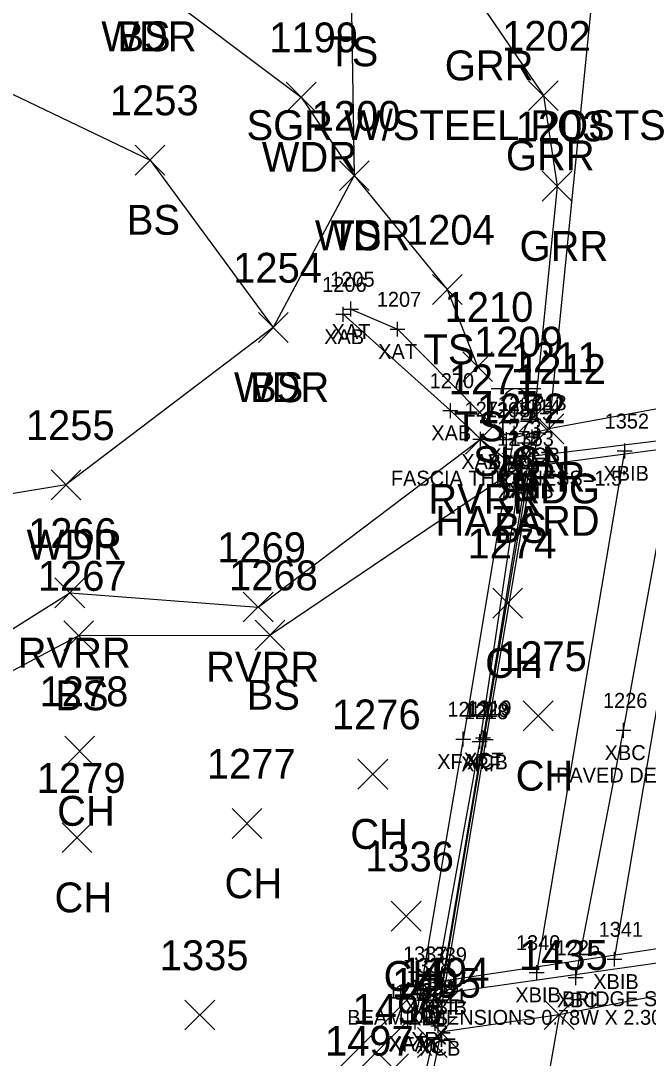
# Model space of a CAD drawing. Extents: x 1678553 to 1680768, y 787260 to 792325.
# Drawn here: x 1678655.8 to 1678697.8, y 787518.8 to 787588.2 of the extents above; entities that cross this region are included whole.
import ezdxf

# ---------------------------------------------------------------- set-up
doc = ezdxf.new("R2010")
doc.units = 0
for name, color, linetype in [('B_A', 7, 'Continuous'), ('B_C', 7, 'Continuous'), ('B_I', 7, 'Continuous'), ('B_TIC', 7, 'Continuous'), ('BB', 7, 'Continuous'), ('BDC', 7, 'Continuous'), ('BELB', 7, 'Continuous'), ('BF', 7, 'Continuous'), ('BR', 7, 'Continuous'), ('BSE', 7, 'Continuous'), ('BSUBM', 7, 'Continuous'), ('Default', 7, 'Continuous'), ('L_A', 7, 'Continuous'), ('L_I', 7, 'Continuous'), ('L_TIC', 7, 'Continuous'), ('LAWA', 7, 'Continuous'), ('LAWE', 7, 'Continuous'), ('LELB', 7, 'Continuous'), ('P_A', 7, 'Continuous'), ('P_I', 7, 'Continuous'), ('P_TIC', 7, 'Continuous'), ('PEU', 7, 'Continuous'), ('PRC', 7, 'Continuous'), ('R_A', 7, 'Continuous'), ('R_C', 7, 'Continuous'), ('R_I', 7, 'Continuous'), ('R_TIC', 7, 'Continuous'), ('RGR', 7, 'Continuous'), ('S_A', 7, 'Continuous'), ('S_C', 7, 'Continuous'), ('S_I', 7, 'Continuous'), ('SSGN', 7, 'Continuous')]:
    doc.layers.add(name, color=color, linetype=linetype)

msp = doc.modelspace()

# ---------------------------------------------------------------- linework, layer by layer
at = {"layer": 'B_TIC'}
for p, q in [((1678677.4, 787568.583), (1678677.475, 787568.583)), ((1678677.914, 787568.928), (1678677.989, 787568.928)), ((1678681.033, 787567.585), (1678681.109, 787567.585)), ((1678684.578, 787562.134), (1678684.653, 787562.134)), ((1678686.588, 787560.22), (1678686.664, 787560.22)), ((1678688.339, 787560.19), (1678688.414, 787560.19)), ((1678688.85, 787560.608), (1678688.925, 787560.608)), ((1678689.542, 787559.98), (1678689.617, 787559.98)), ((1678690.053, 787560.377), (1678690.129, 787560.377)), ((1678690.446, 787560.654), (1678690.521, 787560.654)), ((1678696.259, 787559.432), (1678696.334, 787559.432)), ((1678689.047, 787558.968), (1678689.122, 787558.968)), ((1678689.052, 787558.274), (1678689.127, 787558.274)), ((1678689.879, 787558.254), (1678689.955, 787558.254)), ((1678696.175, 787540.725), (1678696.25, 787540.725)), ((1678685.437, 787540.133), (1678685.512, 787540.133)), ((1678686.54, 787539.97), (1678686.615, 787539.97)), ((1678686.764, 787540.216), (1678686.84, 787540.216)), ((1678686.941, 787540.102), (1678687.017, 787540.102)), ((1678695.575, 787525.394), (1678695.65, 787525.394)), ((1678690.359, 787524.501), (1678690.434, 787524.501)), ((1678692.973, 787524.163), (1678693.048, 787524.163)), ((1678682.753, 787523.742), (1678682.828, 787523.742)), ((1678684.062, 787523.687), (1678684.137, 787523.687)), ((1678683.003, 787522.966), (1678683.078, 787522.966)), ((1678681.721, 787521.255), (1678681.796, 787521.255)), ((1678682.207, 787521.192), (1678682.283, 787521.192)), ((1678683.19, 787521.52), (1678683.266, 787521.52)), ((1678683.552, 787521.092), (1678683.628, 787521.092)), ((1678683.768, 787520.937), (1678683.843, 787520.937))]:
    msp.add_line(p, q, dxfattribs=at)
for points in [[(1678677.396, 787568.083), (1678677.396, 787569.083)], [(1678677.91, 787568.428), (1678677.91, 787569.428)], [(1678676.896, 787568.583), (1678677.896, 787568.583)], [(1678677.41, 787568.928), (1678678.41, 787568.928)], [(1678681.03, 787567.085), (1678681.03, 787568.085)], [(1678680.53, 787567.585), (1678681.53, 787567.585)], [(1678684.074, 787562.134), (1678685.074, 787562.134)], [(1678684.574, 787561.634), (1678684.574, 787562.634)], [(1678686.585, 787559.72), (1678686.585, 787560.72)], [(1678688.335, 787559.69), (1678688.335, 787560.69)], [(1678688.846, 787560.108), (1678688.846, 787561.108)], [(1678690.05, 787559.877), (1678690.05, 787560.877)], [(1678690.442, 787560.154), (1678690.442, 787561.154)], [(1678686.085, 787560.22), (1678687.085, 787560.22)], [(1678687.835, 787560.19), (1678688.835, 787560.19)], [(1678688.346, 787560.608), (1678689.346, 787560.608)], [(1678689.038, 787559.98), (1678690.038, 787559.98)], [(1678689.538, 787559.48), (1678689.538, 787560.48)], [(1678689.55, 787560.377), (1678690.55, 787560.377)], [(1678689.942, 787560.654), (1678690.942, 787560.654)], [(1678689.043, 787558.468), (1678689.043, 787559.468)], [(1678695.755, 787559.432), (1678696.755, 787559.432)], [(1678696.255, 787558.932), (1678696.255, 787559.932)], [(1678688.543, 787558.968), (1678689.543, 787558.968)], [(1678689.048, 787557.774), (1678689.048, 787558.774)], [(1678689.876, 787557.754), (1678689.876, 787558.754)], [(1678688.548, 787558.274), (1678689.548, 787558.274)], [(1678689.376, 787558.254), (1678690.376, 787558.254)], [(1678696.171, 787540.225), (1678696.171, 787541.225)], [(1678685.433, 787539.633), (1678685.433, 787540.633)], [(1678686.761, 787539.716), (1678686.761, 787540.716)], [(1678686.938, 787539.602), (1678686.938, 787540.602)], [(1678695.671, 787540.725), (1678696.671, 787540.725)], [(1678684.933, 787540.133), (1678685.933, 787540.133)], [(1678686.036, 787539.97), (1678687.036, 787539.97)], [(1678686.261, 787540.216), (1678687.261, 787540.216)], [(1678686.438, 787540.102), (1678687.438, 787540.102)], [(1678686.536, 787539.47), (1678686.536, 787540.47)], [(1678695.071, 787525.394), (1678696.071, 787525.394)], [(1678695.571, 787524.894), (1678695.571, 787525.894)], [(1678690.355, 787524.001), (1678690.355, 787525.001)], [(1678692.969, 787523.663), (1678692.969, 787524.663)], [(1678682.749, 787523.242), (1678682.749, 787524.242)], [(1678684.058, 787523.187), (1678684.058, 787524.187)], [(1678689.855, 787524.501), (1678690.855, 787524.501)], [(1678692.469, 787524.163), (1678693.469, 787524.163)], [(1678682.249, 787523.742), (1678683.249, 787523.742)], [(1678682.999, 787522.466), (1678682.999, 787523.466)], [(1678683.558, 787523.687), (1678684.558, 787523.687)], [(1678682.499, 787522.966), (1678683.499, 787522.966)], [(1678681.717, 787520.755), (1678681.717, 787521.755)], [(1678683.187, 787521.02), (1678683.187, 787522.02)], [(1678681.217, 787521.255), (1678682.217, 787521.255)], [(1678681.704, 787521.192), (1678682.704, 787521.192)], [(1678682.204, 787520.692), (1678682.204, 787521.692)], [(1678682.687, 787521.52), (1678683.687, 787521.52)], [(1678683.049, 787521.092), (1678684.049, 787521.092)], [(1678683.549, 787520.592), (1678683.549, 787521.592)], [(1678683.764, 787520.437), (1678683.764, 787521.437)], [(1678683.264, 787520.937), (1678684.264, 787520.937)]]:
    msp.add_lwpolyline(points, dxfattribs=at)
at = {"layer": 'BB'}
for points in [[(1678690.355, 787524.501), (1678696.255, 787559.432)], [(1678695.571, 787525.394), (1678701.411, 787559.95)], [(1678684.058, 787523.687), (1678689.876, 787558.254)]]:
    msp.add_lwpolyline(points, dxfattribs=at)
at = {"layer": 'BDC'}
for points in [[(1678690.05, 787560.377), (1678686.761, 787540.216), (1678683.549, 787521.092)], [(1678690.442, 787560.654), (1678686.938, 787540.102), (1678683.764, 787520.937)]]:
    msp.add_lwpolyline(points, dxfattribs=at)
at = {"layer": 'BELB'}
msp.add_lwpolyline([(1678692.969, 787524.163), (1678696.171, 787540.725), (1678699.562, 787559.385)], dxfattribs=at)
at = {"layer": 'BF'}
msp.add_lwpolyline([(1678688.846, 787560.608), (1678685.433, 787540.133), (1678682.204, 787521.192)], dxfattribs=at)
at = {"layer": 'BR'}
msp.add_lwpolyline([(1678689.538, 787559.98), (1678686.536, 787539.97), (1678683.187, 787521.52)], dxfattribs=at)
at = {"layer": 'BSE'}
for points in [[(1678689.043, 787558.968), (1678708.824, 787561.383)], [(1678682.999, 787522.966), (1678702.689, 787525.745)]]:
    msp.add_lwpolyline(points, dxfattribs=at)
at = {"layer": 'BSUBM'}
for points in [[(1678677.396, 787568.583), (1678684.574, 787562.134), (1678686.585, 787560.22), (1678689.048, 787558.274), (1678709.073, 787560.939), (1678717.011, 787573.607), (1678720.9, 787579.967), (1678722.669, 787582.686)], [(1678677.91, 787568.928), (1678681.03, 787567.585), (1678688.335, 787560.19)], [(1678669.621, 787510.644), (1678682.749, 787523.742), (1678702.286, 787526.696), (1678709.309, 787522.854), (1678710.45, 787522.307), (1678722.702, 787515.164), (1678722.009, 787513.547)], [(1678681.717, 787521.255), (1678672.284, 787511.834)]]:
    msp.add_lwpolyline(points, dxfattribs=at)
at = {"layer": 'Default'}
msp.add_line((1678688.335, 787560.19), (1678691.169, 787560.916), dxfattribs=at)
at = {"layer": 'L_TIC'}
for points in [[(1678673.572, 787582.123), (1678675.572, 787584.123)], [(1678675.572, 787582.123), (1678673.572, 787584.123)], [(1678663.452, 787577.908), (1678665.452, 787579.908)], [(1678665.452, 787577.908), (1678663.452, 787579.908)], [(1678677.136, 787576.869), (1678679.136, 787578.869)], [(1678679.136, 787576.869), (1678677.136, 787578.869)], [(1678677.136, 787576.869), (1678679.136, 787578.869)], [(1678679.136, 787576.869), (1678677.136, 787578.869)], [(1678683.365, 787569.236), (1678685.365, 787571.236)], [(1678685.365, 787569.236), (1678683.365, 787571.236)], [(1678671.711, 787566.697), (1678673.711, 787568.697)], [(1678673.711, 787566.697), (1678671.711, 787568.697)], [(1678671.711, 787566.697), (1678673.711, 787568.697)], [(1678673.711, 787566.697), (1678671.711, 787568.697)], [(1678685.397, 787564.076), (1678687.397, 787566.076)], [(1678687.397, 787564.076), (1678685.397, 787566.076)], [(1678685.585, 787559.22), (1678687.585, 787561.22)], [(1678687.585, 787559.22), (1678685.585, 787561.22)], [(1678688.048, 787557.274), (1678690.048, 787559.274)], [(1678690.048, 787557.274), (1678688.048, 787559.274)], [(1678657.82, 787556.155), (1678659.82, 787558.155)], [(1678659.82, 787556.155), (1678657.82, 787558.155)], [(1678658.072, 787548.926), (1678660.072, 787550.926)], [(1678660.072, 787548.926), (1678658.072, 787550.926)], [(1678670.697, 787547.979), (1678672.697, 787549.979)], [(1678672.697, 787547.979), (1678670.697, 787549.979)], [(1678687.416, 787548.231), (1678689.416, 787550.231)], [(1678689.416, 787548.231), (1678687.416, 787550.231)], [(1678658.671, 787546.063), (1678660.671, 787548.063)], [(1678660.671, 787546.063), (1678658.671, 787548.063)], [(1678671.485, 787546.096), (1678673.485, 787548.096)], [(1678673.485, 787546.096), (1678671.485, 787548.096)], [(1678689.459, 787540.685), (1678691.459, 787542.685)], [(1678691.459, 787540.685), (1678689.459, 787542.685)], [(1678658.738, 787538.328), (1678660.738, 787540.328)], [(1678660.738, 787538.328), (1678658.738, 787540.328)], [(1678678.382, 787536.784), (1678680.382, 787538.784)], [(1678680.382, 787536.784), (1678678.382, 787538.784)], [(1678669.951, 787533.479), (1678671.951, 787535.479)], [(1678671.951, 787533.479), (1678669.951, 787535.479)], [(1678658.562, 787532.53), (1678660.562, 787534.53)], [(1678660.562, 787532.53), (1678658.562, 787534.53)], [(1678680.611, 787527.271), (1678682.611, 787529.271)], [(1678682.611, 787527.271), (1678680.611, 787529.271)], [(1678666.791, 787520.658), (1678668.791, 787522.658)], [(1678668.791, 787520.658), (1678666.791, 787522.658)], [(1678679.77, 787517.059), (1678681.77, 787519.059)], [(1678681.77, 787517.059), (1678679.77, 787519.059)]]:
    msp.add_lwpolyline(points, dxfattribs=at)
at = {"layer": 'LAWA'}
msp.add_lwpolyline([(1678599.449, 787627.073), (1678621.625, 787630.476), (1678629.134, 787625.904), (1678659.679, 787623.105), (1678672.049, 787619.874), (1678670.055, 787610.94), (1678664.338, 787597.338), (1678663.823, 787591.2), (1678674.572, 787583.123), (1678678.136, 787577.869), (1678672.711, 787567.697), (1678658.82, 787557.155), (1678637.901, 787553.69), (1678611.83, 787542.757), (1678587.073, 787526.57)], dxfattribs=at)
at = {"layer": 'LAWE'}
msp.add_lwpolyline([(1678587.073, 787526.57), (1678606.59, 787527.872), (1678618.014, 787527.662), (1678640.226, 787538.083), (1678659.072, 787549.926), (1678671.697, 787548.979), (1678686.585, 787560.22)], dxfattribs=at)
at = {"layer": 'LELB'}
for points in [[(1678677.92, 787590.192), (1678678.136, 787577.869), (1678684.365, 787570.236), (1678686.397, 787565.076)], [(1678585.998, 787548.348), (1678627.662, 787567.106), (1678650.828, 787585.414), (1678664.452, 787578.908), (1678672.711, 787567.697)], [(1678586.054, 787523.104), (1678605.17, 787525.671), (1678618.579, 787526.795), (1678639.455, 787536.365), (1678659.671, 787547.063), (1678672.485, 787547.096), (1678689.048, 787558.274)]]:
    msp.add_lwpolyline(points, dxfattribs=at)
at = {"layer": 'P_TIC'}
for points in [[(1678690.169, 787559.916), (1678692.169, 787561.916)], [(1678692.169, 787559.916), (1678690.169, 787561.916)], [(1678690.169, 787559.916), (1678692.169, 787561.916)], [(1678692.169, 787559.916), (1678690.169, 787561.916)], [(1678690.863, 787520.675), (1678692.863, 787522.675)], [(1678692.863, 787520.675), (1678690.863, 787522.675)], [(1678690.863, 787520.675), (1678692.863, 787522.675)], [(1678692.863, 787520.675), (1678690.863, 787522.675)], [(1678682.928, 787519.501), (1678684.928, 787521.501)], [(1678684.928, 787519.501), (1678682.928, 787521.501)]]:
    msp.add_lwpolyline(points, dxfattribs=at)
at = {"layer": 'PEU'}
for points in [[(1678707.071, 787835.603), (1678708.867, 787801.612), (1678711.158, 787769.032), (1678713.635, 787732.076), (1678713.931, 787704.33), (1678716.279, 787671.407), (1678712.683, 787651.273), (1678711.57, 787636.622), (1678710.351, 787611.373), (1678708.977, 787582.71), (1678707.824, 787563.264), (1678700.138, 787562.553), (1678691.169, 787560.916)], [(1678689.058, 787834.793), (1678688.671, 787796.642), (1678691.647, 787771.507), (1678695.197, 787739.732), (1678696.507, 787702.348), (1678697.464, 787665.848), (1678696.677, 787633.808), (1678695.099, 787616.534), (1678694.509, 787594.402), (1678691.169, 787560.916)], [(1678701.084, 787523.46), (1678691.863, 787521.675), (1678683.928, 787520.501), (1678679.423, 787498.085), (1678675.858, 787484.768), (1678672.353, 787466.03), (1678666.651, 787446.983), (1678662.975, 787430.653), (1678658.139, 787412.595), (1678657.115, 787400.242), (1678651.997, 787380.889), (1678646.796, 787355.993), (1678640.868, 787332.433), (1678631.508, 787300.964), (1678626.743, 787281.591)]]:
    msp.add_lwpolyline(points, dxfattribs=at)
at = {"layer": 'PRC'}
msp.add_lwpolyline([(1678691.863, 787521.675), (1678687.471, 787496.537), (1678683.409, 787472.735), (1678673.582, 787430.342), (1678667.066, 787403.394), (1678661.63, 787379.176), (1678654.8, 787353.827), (1678646.933, 787323.808), (1678641.795, 787300.306), (1678636.187, 787278.722)], dxfattribs=at)
at = {"layer": 'R_TIC'}
for points in [[(1678689.806, 787582.226), (1678691.806, 787584.226)], [(1678691.806, 787582.226), (1678689.806, 787584.226)], [(1678690.719, 787576.161), (1678692.719, 787578.161)], [(1678692.719, 787576.161), (1678690.719, 787578.161)], [(1678689.182, 787560.699), (1678691.182, 787562.699)], [(1678691.182, 787560.699), (1678689.182, 787562.699)], [(1678682.363, 787518.815), (1678684.363, 787520.815)], [(1678684.363, 787518.815), (1678682.363, 787520.815)]]:
    msp.add_lwpolyline(points, dxfattribs=at)
at = {"layer": 'RGR'}
for points in [[(1678686.71, 787589.248), (1678690.806, 787583.226), (1678691.719, 787577.161), (1678690.182, 787561.699)], [(1678683.363, 787519.815), (1678678.582, 787498.569), (1678674.343, 787485.377), (1678670.471, 787477.811)]]:
    msp.add_lwpolyline(points, dxfattribs=at)
at = {"layer": 'SSGN'}
for p, q in [((1678687.31, 787563.601), (1678690.644, 787563.601)), ((1678688.957, 787562.768), (1678688.957, 787562.768))]:
    msp.add_line(p, q, dxfattribs=at)
msp.add_circle((1678688.957, 787562.768), 0.833, dxfattribs=at)

# ---------------------------------------------------------------- texts
at = {"layer": 'B_A'}
for s, p in [('XAT', (1678676.615, 787566.928)), ('XAB', (1678676.117, 787566.583)), ('XAT', (1678679.735, 787565.585)), ('XAB', (1678683.295, 787560.134)), ('XFAT', (1678687.102, 787558.608)), ('XCT', (1678688.77, 787558.377)), ('XCB', (1678689.178, 787558.654)), ('XAB', (1678685.305, 787558.22)), ('XAT', (1678687.04, 787558.19)), ('XRF', (1678688.298, 787557.98)), ('XBS', (1678687.783, 787556.968)), ('XBIB', (1678694.826, 787557.432)), ('XAB', (1678687.769, 787556.274)), ('XBIB', (1678688.447, 787556.254)), ('XFAT', (1678683.689, 787538.133)), ('XCT', (1678685.481, 787538.216)), ('XBC', (1678694.908, 787538.725)), ('XRF', (1678685.296, 787537.97)), ('XCB', (1678685.674, 787538.102)), ('XBIB', (1678694.142, 787523.394)), ('XBIB', (1678688.926, 787522.501)), ('XBC', (1678691.705, 787522.163)), ('XAB', (1678681.47, 787521.742)), ('XBIB', (1678682.629, 787521.687)), ('XBS', (1678681.739, 787520.966)), ('XRF', (1678681.946, 787519.52)), ('XAT', (1678680.422, 787519.255)), ('XFAT', (1678680.46, 787519.192)), ('XCT', (1678682.269, 787519.092)), ('XCB', (1678682.5, 787518.937))]:
    msp.add_text(s, height=1, dxfattribs=at).set_placement(p)
at = {"layer": 'B_C'}
for s, p in [("FASCIA THICKNESS=1.5'", (1678680.587, 787557.108)), ('PAVED DECK', (1678691.652, 787537.225)), ("BRIDGE SEAT DEPTH = 0.85'", (1678692.044, 787522.245)), ('BEAM DIMENSIONS 0.78W X 2.30H', (1678677.663, 787521.001))]:
    msp.add_text(s, height=1, dxfattribs=at).set_placement(p)
at = {"layer": 'B_I'}
for s, p in [('1206', (1678675.983, 787570.083)), ('1205', (1678676.524, 787570.428)), ('1207', (1678679.644, 787569.085)), ('1270', (1678683.185, 787563.634)), ('1216', (1678687.756, 787562.108)), ('1214', (1678688.987, 787561.877)), ('1213', (1678689.379, 787562.154)), ('1271', (1678685.522, 787561.72)), ('1208', (1678686.95, 787561.69)), ('1215', (1678688.476, 787561.48)), ('1273', (1678687.697, 787560.468)), ('1352', (1678694.909, 787560.932)), ('1272', (1678687.702, 787559.774)), ('1353', (1678688.529, 787559.754)), ('1217', (1678684.37, 787541.633)), ('1220', (1678685.548, 787541.602)), ('1219', (1678685.694, 787541.716)), ('1226', (1678694.798, 787542.225)), ('1218', (1678685.473, 787541.47)), ('1341', (1678694.508, 787526.894)), ('1340', (1678688.966, 787526.001)), ('1225', (1678691.623, 787525.663)), ('1337', (1678681.403, 787525.242)), ('1339', (1678682.708, 787525.187)), ('1338', (1678681.653, 787524.466)), ('1223', (1678681.84, 787523.02)), ('1242', (1678680.371, 787522.755)), ('1224', (1678680.858, 787522.692)), ('1222', (1678682.203, 787522.592)), ('1221', (1678682.701, 787522.437))]:
    msp.add_text(s, height=1, dxfattribs=at).set_placement(p)
at = {"layer": 'L_A'}
for s, p in [('WDR', (1678661.185, 787586.2)), ('BS', (1678662.264, 787586.2)), ('TS', (1678676.329, 787585.192)), ('WDR', (1678671.934, 787578.123)), ('BS', (1678662.893, 787573.908)), ('WDR', (1678675.498, 787572.869)), ('TS', (1678676.545, 787572.869)), ('TS', (1678682.775, 787565.236)), ('WDR', (1678670.073, 787562.697)), ('BS', (1678671.152, 787562.697)), ('TS', (1678684.806, 787560.076)), ('RVRR', (1678683.097, 787555.22)), ('BS', (1678687.489, 787553.274)), ('WDR', (1678656.183, 787552.155)), ('RVRR', (1678655.584, 787544.926)), ('CH', (1678686.904, 787544.231)), ('RVRR', (1678668.208, 787543.979)), ('BS', (1678658.112, 787542.063)), ('BS', (1678670.926, 787542.096)), ('CH', (1678688.948, 787536.685)), ('CH', (1678658.226, 787534.328)), ('CH', (1678677.87, 787532.784)), ('CH', (1678669.439, 787529.479)), ('CH', (1678658.05, 787528.53)), ('CH', (1678680.099, 787523.271))]:
    msp.add_text(s, height=2, dxfattribs=at).set_placement(p)
at = {"layer": 'L_I'}
for s, p in [('1199', (1678672.438, 787586.123)), ('1253', (1678661.759, 787581.908)), ('1200', (1678675.278, 787580.869)), ('1200', (1678675.278, 787580.869)), ('1204', (1678681.594, 787573.236)), ('1254', (1678670.019, 787570.697)), ('1254', (1678670.019, 787570.697)), ('1210', (1678684.185, 787568.076)), ('1271', (1678684.459, 787563.22)), ('1272', (1678686.355, 787561.274)), ('1255', (1678656.128, 787560.155)), ('1266', (1678656.277, 787552.926)), ('1269', (1678668.949, 787551.979)), ('1274', (1678685.723, 787552.231)), ('1267', (1678656.931, 787550.063)), ('1268', (1678669.745, 787550.096)), ('1275', (1678687.767, 787544.685)), ('1278', (1678657.045, 787542.328)), ('1276', (1678676.634, 787540.784)), ('1277', (1678668.258, 787537.479)), ('1279', (1678656.862, 787536.53)), ('1336', (1678678.863, 787531.271)), ('1335', (1678665.099, 787524.658)), ('1496', (1678678.022, 787521.059)), ('1497', (1678676.172, 787518.928))]:
    msp.add_text(s, height=2, dxfattribs=at).set_placement(p)
at = {"layer": 'P_A'}
msp.add_text('RDG', height=2, dxfattribs=at).set_placement((1678688.657, 787555.916))
msp.add_text('RDG', height=2, dxfattribs=at).set_placement((1678688.657, 787555.916))
at = {"layer": 'P_I'}
for s, p in [('1212', (1678689.043, 787563.916)), ('1212', (1678689.043, 787563.916)), ('1435', (1678689.171, 787524.675)), ('1435', (1678689.171, 787524.675)), ('1494', (1678681.235, 787523.501))]:
    msp.add_text(s, height=2, dxfattribs=at).set_placement(p)
at = {"layer": 'R_A'}
for p in [(1678684.198, 787584.248), (1678688.294, 787578.226), (1678689.207, 787572.161), (1678687.67, 787556.699)]:
    msp.add_text('GRR', height=2, dxfattribs=at).set_placement(p)
at = {"layer": 'R_C'}
msp.add_text('SGR W/STEEL POSTS', height=2, dxfattribs=at).set_placement((1678670.915, 787580.248))
at = {"layer": 'R_I'}
for s, p in [('1202', (1678688.035, 787586.226)), ('1203', (1678688.948, 787580.161)), ('1211', (1678688.623, 787564.699)), ('1495', (1678680.67, 787522.815))]:
    msp.add_text(s, height=2, dxfattribs=at).set_placement(p)
at = {"layer": 'S_A'}
msp.add_text('SIGN', height=2, dxfattribs=at).set_placement((1678686.095, 787557.748))
at = {"layer": 'S_C'}
msp.add_text('HAZARD', height=2, dxfattribs=at).set_placement((1678683.576, 787553.748))
at = {"layer": 'S_I'}
msp.add_text('1209', height=2, dxfattribs=at).set_placement((1678686.158, 787565.748))

doc.saveas('drawing.dxf')
